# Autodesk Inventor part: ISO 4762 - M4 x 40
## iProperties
Library Location: C:\Program Files\Autodesk\Inventor 6\content
Library: local
SubLibrary: ISO
Family: 13
Member: 460
Member Major Revision: 1
Member Minor Revision: 1
Comments: To add or edit properties for Autodesk Inventor files, use iProperties.
Created: 2003-05
Part Number: ISO 4762 - M4 x 40
Vendor: Autodesk Inc.
Document SubType Name: Modeling
Designer: Philippe
Description: Vis cylindrique à six pans creux
Standard: ISO 4762 M4 x 40
Alert: To add or edit properties for Autodesk Inventor files, use iProperties.
Control State: 0
Master: False
Checked Out: False
Shininess: 64.0
Length Units: 11269
Angle Units: 11279
Time Units: 11290
Mass Units: 11283
Length Display Precision: 3
Angle Display Precision: 2
Compacted: True
EGR: 1
Density: 0.0
Volumn: 0.0
Area: 0.0
PropertySet Name: Model Information
Author: Philippe
Revision Number: 1
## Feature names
1. Corps [Revolution]
2. Fente [Extrusion]
3. Congé1 [Fillet]
4. Chanfrein1 [Chamfer]
